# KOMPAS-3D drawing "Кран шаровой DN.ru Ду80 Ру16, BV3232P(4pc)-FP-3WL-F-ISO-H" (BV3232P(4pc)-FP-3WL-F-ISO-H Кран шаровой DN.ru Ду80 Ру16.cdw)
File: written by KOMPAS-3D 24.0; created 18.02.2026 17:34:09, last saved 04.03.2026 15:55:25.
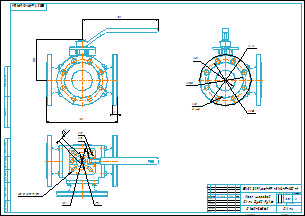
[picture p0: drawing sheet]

Document properties: Автор: R2D2; Форматы листов документа: A2; Полное имя файла: BV3232P(4pc)-FP-3WL-F-ISO-H Кран шаровой DN.ru Ду80 Ру16.m3d; Масса: 39.1; Наименование: Кран шаровой DN.ru Ду80 Ру16; Количество листов документа: 1; Примечание: D160-36362

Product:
- Part/product: Кран шаровой DN.ru Ду80 Ру16  | designation BV3232P(4pc)-FP-3WL-F-ISO-H
    Масса: 39.1
    Раздел спецификации: Прочие изделия
    Примечание: D160-36362

Views: Проекционный вид 2
Referenced files in E:\Работа\Зайцев\BV3232P(4pc)-FP-3WL-F-ISO-H Кран шаровой DN.ru Ду15-100 Ру16\DN80\: BV3232P(4pc)-FP-3WL-F-ISO-H Кран шаровой DN.ru Ду80 Ру16.m3d
Referenced files in E:\Работа\Зайцев\Для компаса\: чертеж DN.ru А3.cdt
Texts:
  BV3232P(4pc)-FP-3WL-F-ISO-H
  чертеж DN.ru А3.cdt
  Кран шаровой
  DN.ru Ду80 Ру16
  Кран шаровой DN.ru Ду80 Ру16
  BV3232P(4pc)-FP-3WL-F-ISO-H Кран шаровой DN.ru Ду80 Ру16
Dimensions and other numbers on the sheet: 0; 3; 4; 200; 160; 138; 18; 8 отв.; 80; 1:2; 1; 2; 39,1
